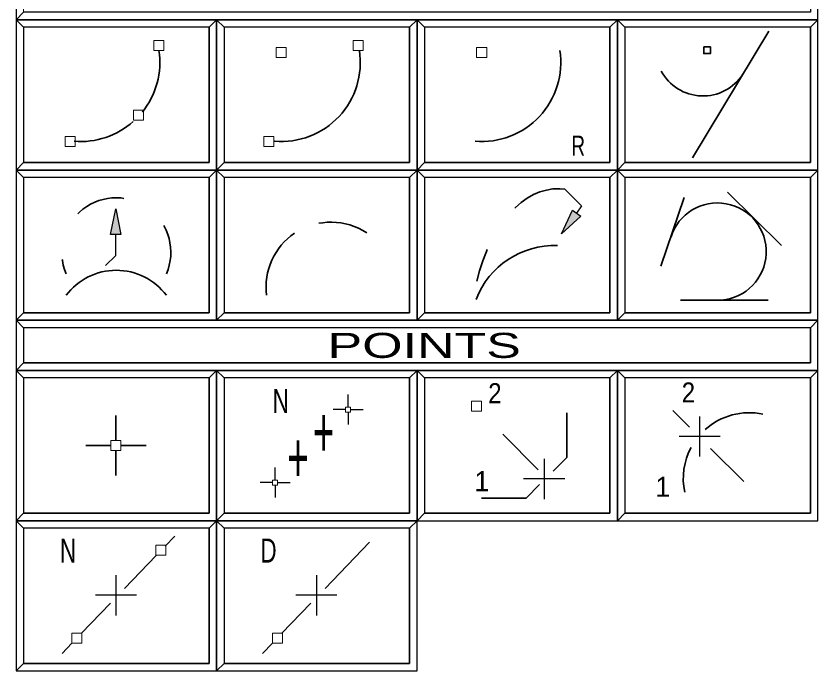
# Model space of a CAD drawing. Extents: x 95906.9 to 95918.9, y 90964.8 to 90972.9.
# Drawn here: x 95910.832 to 95912.432, y 90967.362 to 90968.669 of the extents above; entities that cross this region are included whole.
import ezdxf
from ezdxf.enums import TextEntityAlignment as Align

# ---------------------------------------------------------------- set-up
doc = ezdxf.new("R2010")
doc.units = 0
doc.header["$LTSCALE"] = 0.019
doc.linetypes.add('MEDIUM_DASHED', pattern=[4.5, 3, -1.5])
for name, color, linetype, lineweight in [('1', 7, 'Continuous', 25), ('11', 7, 'Continuous', 25), ('12', 7, 'Continuous', 25), ('17', 7, 'Continuous', 25), ('2', 7, 'Continuous', 13), ('3', 7, 'Continuous', 25), ('4', 7, 'Continuous', 35), ('6', 7, 'Continuous', 35), ('7', 7, 'Continuous', 35)]:
    doc.layers.add(name, color=color, linetype=linetype, lineweight=lineweight)

msp = doc.modelspace()

# ---------------------------------------------------------------- hatches: boundary and pattern name
at = {"layer": '6'}
for points in [[(95911.0204, 90968.2331), (95911.0306, 90968.2843), (95911.0408, 90968.2331)], [(95911.9585, 90968.2697), (95911.92, 90968.2344), (95911.9421, 90968.2817)]]:
    msp.add_hatch(color=256, dxfattribs=at).paths.add_polyline_path(points)

# ---------------------------------------------------------------- linework, layer by layer
at = {"layer": '1'}
for points in [[(95910.8318, 90968.6617), (95912.4318, 90968.6617), (95912.4318, 90968.7617), (95910.8318, 90968.7617)], [(95910.8318, 90968.3617), (95911.2318, 90968.3617), (95911.2318, 90968.6617), (95910.8318, 90968.6617)], [(95911.2318, 90968.3617), (95911.6318, 90968.3617), (95911.6318, 90968.6617), (95911.2318, 90968.6617)], [(95911.6318, 90968.3617), (95912.0318, 90968.3617), (95912.0318, 90968.6617), (95911.6318, 90968.6617)], [(95912.0318, 90968.3617), (95912.4318, 90968.3617), (95912.4318, 90968.6617), (95912.0318, 90968.6617)], [(95910.8318, 90968.0617), (95911.2318, 90968.0617), (95911.2318, 90968.3617), (95910.8318, 90968.3617)], [(95911.2318, 90968.0617), (95911.6318, 90968.0617), (95911.6318, 90968.3617), (95911.2318, 90968.3617)], [(95911.6318, 90968.0617), (95912.0318, 90968.0617), (95912.0318, 90968.3617), (95911.6318, 90968.3617)], [(95912.0318, 90968.0617), (95912.4318, 90968.0617), (95912.4318, 90968.3617), (95912.0318, 90968.3617)], [(95910.8318, 90967.9617), (95912.4318, 90967.9617), (95912.4318, 90968.0617), (95910.8318, 90968.0617)], [(95910.8318, 90967.6617), (95911.2318, 90967.6617), (95911.2318, 90967.9617), (95910.8318, 90967.9617)], [(95911.2318, 90967.6617), (95911.6318, 90967.6617), (95911.6318, 90967.9617), (95911.2318, 90967.9617)], [(95911.6318, 90967.6617), (95912.0318, 90967.6617), (95912.0318, 90967.9617), (95911.6318, 90967.9617)], [(95912.0318, 90967.6617), (95912.4318, 90967.6617), (95912.4318, 90967.9617), (95912.0318, 90967.9617)], [(95910.8318, 90967.3617), (95911.2318, 90967.3617), (95911.2318, 90967.6617), (95910.8318, 90967.6617)], [(95911.2318, 90967.3617), (95911.6318, 90967.3617), (95911.6318, 90967.6617), (95911.2318, 90967.6617)]]:
    msp.add_lwpolyline(points, close=True, dxfattribs=at)
at = {"layer": '11'}
for points in [[(95910.8468, 90968.3767), (95911.2168, 90968.3767), (95911.2168, 90968.6467), (95910.8468, 90968.6467)], [(95911.2468, 90968.3767), (95911.6168, 90968.3767), (95911.6168, 90968.6467), (95911.2468, 90968.6467)], [(95911.6468, 90968.3767), (95912.0168, 90968.3767), (95912.0168, 90968.6467), (95911.6468, 90968.6467)], [(95912.0468, 90968.3767), (95912.4168, 90968.3767), (95912.4168, 90968.6467), (95912.0468, 90968.6467)], [(95910.8468, 90968.0767), (95911.2168, 90968.0767), (95911.2168, 90968.3467), (95910.8468, 90968.3467)], [(95911.2468, 90968.0767), (95911.6168, 90968.0767), (95911.6168, 90968.3467), (95911.2468, 90968.3467)], [(95911.6468, 90968.0767), (95912.0168, 90968.0767), (95912.0168, 90968.3467), (95911.6468, 90968.3467)], [(95912.0468, 90968.0767), (95912.4168, 90968.0767), (95912.4168, 90968.3467), (95912.0468, 90968.3467)], [(95910.8468, 90967.6767), (95911.2168, 90967.6767), (95911.2168, 90967.9467), (95910.8468, 90967.9467)], [(95911.2468, 90967.6767), (95911.6168, 90967.6767), (95911.6168, 90967.9467), (95911.2468, 90967.9467)], [(95911.6468, 90967.6767), (95912.0168, 90967.6767), (95912.0168, 90967.9467), (95911.6468, 90967.9467)], [(95912.0468, 90967.6767), (95912.4168, 90967.6767), (95912.4168, 90967.9467), (95912.0468, 90967.9467)], [(95910.8468, 90967.3767), (95911.2168, 90967.3767), (95911.2168, 90967.6467), (95910.8468, 90967.6467)], [(95911.2468, 90967.3767), (95911.6168, 90967.3767), (95911.6168, 90967.6467), (95911.2468, 90967.6467)]]:
    msp.add_lwpolyline(points, close=True, dxfattribs=at)
at = {"layer": '12'}
for points in [[(95910.8468, 90968.3767), (95911.2168, 90968.3767), (95911.2168, 90968.6467), (95910.8468, 90968.6467)], [(95910.8468, 90967.6767), (95911.2168, 90967.6767), (95911.2168, 90967.9467), (95910.8468, 90967.9467)]]:
    msp.add_lwpolyline(points, close=True, dxfattribs=at)
at = {"layer": '17'}
msp.add_lwpolyline([(95910.8468, 90967.9767), (95912.4168, 90967.9767), (95912.4168, 90968.0467), (95910.8468, 90968.0467)], close=True, dxfattribs=at)
at = {"layer": '2'}
for points in [[(95910.8318, 90968.7617), (95910.8318, 90968.6617), (95910.8468, 90968.6767), (95910.8468, 90968.7467), (95912.4168, 90968.7467), (95912.4318, 90968.7617)], [(95910.8318, 90968.6617), (95910.8318, 90968.3617), (95910.8468, 90968.3767), (95910.8468, 90968.6467), (95911.2168, 90968.6467), (95911.2318, 90968.6617)], [(95911.2318, 90968.6617), (95911.2318, 90968.3617), (95911.2468, 90968.3767), (95911.2468, 90968.6467), (95911.6168, 90968.6467), (95911.6318, 90968.6617)], [(95911.6318, 90968.6617), (95911.6318, 90968.3617), (95911.6468, 90968.3767), (95911.6468, 90968.6467), (95912.0168, 90968.6467), (95912.0318, 90968.6617)], [(95912.0318, 90968.6617), (95912.0318, 90968.3617), (95912.0468, 90968.3767), (95912.0468, 90968.6467), (95912.4168, 90968.6467), (95912.4318, 90968.6617)], [(95910.8318, 90968.3617), (95910.8318, 90968.0617), (95910.8468, 90968.0767), (95910.8468, 90968.3467), (95911.2168, 90968.3467), (95911.2318, 90968.3617)], [(95911.2318, 90968.3617), (95911.2318, 90968.0617), (95911.2468, 90968.0767), (95911.2468, 90968.3467), (95911.6168, 90968.3467), (95911.6318, 90968.3617)], [(95911.6318, 90968.3617), (95911.6318, 90968.0617), (95911.6468, 90968.0767), (95911.6468, 90968.3467), (95912.0168, 90968.3467), (95912.0318, 90968.3617)], [(95912.0318, 90968.3617), (95912.0318, 90968.0617), (95912.0468, 90968.0767), (95912.0468, 90968.3467), (95912.4168, 90968.3467), (95912.4318, 90968.3617)], [(95910.8318, 90968.0617), (95910.8318, 90967.9617), (95910.8468, 90967.9767), (95910.8468, 90968.0467), (95912.4168, 90968.0467), (95912.4318, 90968.0617)], [(95910.8318, 90967.9617), (95910.8318, 90967.6617), (95910.8468, 90967.6767), (95910.8468, 90967.9467), (95911.2168, 90967.9467), (95911.2318, 90967.9617)], [(95911.2318, 90967.9617), (95911.2318, 90967.6617), (95911.2468, 90967.6767), (95911.2468, 90967.9467), (95911.6168, 90967.9467), (95911.6318, 90967.9617)], [(95911.6318, 90967.9617), (95911.6318, 90967.6617), (95911.6468, 90967.6767), (95911.6468, 90967.9467), (95912.0168, 90967.9467), (95912.0318, 90967.9617)], [(95912.0318, 90967.9617), (95912.0318, 90967.6617), (95912.0468, 90967.6767), (95912.0468, 90967.9467), (95912.4168, 90967.9467), (95912.4318, 90967.9617)], [(95910.8318, 90967.6617), (95910.8318, 90967.3617), (95910.8468, 90967.3767), (95910.8468, 90967.6467), (95911.2168, 90967.6467), (95911.2318, 90967.6617)], [(95911.2318, 90967.6617), (95911.2318, 90967.3617), (95911.2468, 90967.3767), (95911.2468, 90967.6467), (95911.6168, 90967.6467), (95911.6318, 90967.6617)]]:
    msp.add_lwpolyline(points, close=True, dxfattribs=at)
at = {"layer": '3'}
for points in [[(95910.8318, 90968.6617), (95912.4318, 90968.6617), (95912.4318, 90968.7617), (95912.4168, 90968.7467), (95912.4168, 90968.6767), (95910.8468, 90968.6767)], [(95910.8318, 90968.3617), (95911.2318, 90968.3617), (95911.2318, 90968.6617), (95911.2168, 90968.6467), (95911.2168, 90968.3767), (95910.8468, 90968.3767)], [(95911.2318, 90968.3617), (95911.6318, 90968.3617), (95911.6318, 90968.6617), (95911.6168, 90968.6467), (95911.6168, 90968.3767), (95911.2468, 90968.3767)], [(95911.6318, 90968.3617), (95912.0318, 90968.3617), (95912.0318, 90968.6617), (95912.0168, 90968.6467), (95912.0168, 90968.3767), (95911.6468, 90968.3767)], [(95912.0318, 90968.3617), (95912.4318, 90968.3617), (95912.4318, 90968.6617), (95912.4168, 90968.6467), (95912.4168, 90968.3767), (95912.0468, 90968.3767)], [(95910.8318, 90968.0617), (95911.2318, 90968.0617), (95911.2318, 90968.3617), (95911.2168, 90968.3467), (95911.2168, 90968.0767), (95910.8468, 90968.0767)], [(95911.2318, 90968.0617), (95911.6318, 90968.0617), (95911.6318, 90968.3617), (95911.6168, 90968.3467), (95911.6168, 90968.0767), (95911.2468, 90968.0767)], [(95911.6318, 90968.0617), (95912.0318, 90968.0617), (95912.0318, 90968.3617), (95912.0168, 90968.3467), (95912.0168, 90968.0767), (95911.6468, 90968.0767)], [(95912.0318, 90968.0617), (95912.4318, 90968.0617), (95912.4318, 90968.3617), (95912.4168, 90968.3467), (95912.4168, 90968.0767), (95912.0468, 90968.0767)], [(95910.8318, 90967.9617), (95912.4318, 90967.9617), (95912.4318, 90968.0617), (95912.4168, 90968.0467), (95912.4168, 90967.9767), (95910.8468, 90967.9767)], [(95910.8318, 90967.6617), (95911.2318, 90967.6617), (95911.2318, 90967.9617), (95911.2168, 90967.9467), (95911.2168, 90967.6767), (95910.8468, 90967.6767)], [(95911.2318, 90967.6617), (95911.6318, 90967.6617), (95911.6318, 90967.9617), (95911.6168, 90967.9467), (95911.6168, 90967.6767), (95911.2468, 90967.6767)], [(95911.6318, 90967.6617), (95912.0318, 90967.6617), (95912.0318, 90967.9617), (95912.0168, 90967.9467), (95912.0168, 90967.6767), (95911.6468, 90967.6767)], [(95912.0318, 90967.6617), (95912.4318, 90967.6617), (95912.4318, 90967.9617), (95912.4168, 90967.9467), (95912.4168, 90967.6767), (95912.0468, 90967.6767)], [(95910.8318, 90967.3617), (95911.2318, 90967.3617), (95911.2318, 90967.6617), (95911.2168, 90967.6467), (95911.2168, 90967.3767), (95910.8468, 90967.3767)], [(95911.2318, 90967.3617), (95911.6318, 90967.3617), (95911.6318, 90967.6617), (95911.6168, 90967.6467), (95911.6168, 90967.3767), (95911.2468, 90967.3767)]]:
    msp.add_lwpolyline(points, close=True, dxfattribs=at)
at = {"layer": '4'}
for p, q in [((95910.8468, 90968.6467), (95910.8318, 90968.6617)), ((95911.2468, 90968.6467), (95911.2318, 90968.6617)), ((95911.6468, 90968.6467), (95911.6318, 90968.6617)), ((95912.0468, 90968.6467), (95912.0318, 90968.6617)), ((95910.8468, 90968.3467), (95910.8318, 90968.3617)), ((95911.2468, 90968.3467), (95911.2318, 90968.3617)), ((95911.6468, 90968.3467), (95911.6318, 90968.3617)), ((95912.0468, 90968.3467), (95912.0318, 90968.3617)), ((95910.8468, 90968.0467), (95910.8318, 90968.0617)), ((95910.8468, 90967.9467), (95910.8318, 90967.9617)), ((95911.2468, 90967.9467), (95911.2318, 90967.9617)), ((95911.6468, 90967.9467), (95911.6318, 90967.9617)), ((95912.0468, 90967.9467), (95912.0318, 90967.9617)), ((95910.8468, 90967.6467), (95910.8318, 90967.6617)), ((95911.2468, 90967.6467), (95911.2318, 90967.6617))]:
    msp.add_line(p, q, dxfattribs=at)
at = {"layer": '6'}
for p, q in [((95912.1815, 90968.3864), (95912.334, 90968.6387)), ((95912.1182, 90968.1698), (95912.1646, 90968.3071)), ((95912.251, 90968.3178), (95912.3589, 90968.2108)), ((95912.3322, 90968.102), (95912.1574, 90968.102)), ((95912.142, 90967.8817), (95912.1756, 90967.8481)), ((95911.0312, 90967.8216), (95911.0312, 90967.8716)), ((95911.0212, 90967.8116), (95910.9712, 90967.8116)), ((95911.0412, 90967.8116), (95911.0912, 90967.8116)), ((95911.0312, 90967.8016), (95911.0312, 90967.7516)), ((95912.2836, 90967.74), (95912.2176, 90967.8061)), ((95911.1484, 90967.6305), (95911.1295, 90967.6108)), ((95911.4485, 90967.5266), (95911.537, 90967.6188)), ((95911.0485, 90967.5266), (95911.1117, 90967.5924)), ((95910.9617, 90967.4363), (95911.02, 90967.4969)), ((95911.3617, 90967.4363), (95911.42, 90967.4969)), ((95910.9238, 90967.3969), (95910.9434, 90967.4173)), ((95911.3238, 90967.3969), (95911.3434, 90967.4173))]:
    msp.add_line(p, q, dxfattribs=at)
at = {"layer": '6', "lineweight": 25}
for p, q in [((95911.4944, 90967.8886), (95911.4944, 90967.9136)), ((95911.4894, 90967.8836), (95911.4644, 90967.8836)), ((95911.4944, 90967.8786), (95911.4944, 90967.8536)), ((95911.4994, 90967.8836), (95911.5244, 90967.8836)), ((95912.1957, 90967.8699), (95912.1957, 90967.7896)), ((95912.1548, 90967.8305), (95912.2367, 90967.8305)), ((95911.8855, 90967.7853), (95911.8855, 90967.705)), ((95911.3486, 90967.7428), (95911.3486, 90967.7678)), ((95911.8446, 90967.7459), (95911.9265, 90967.7459)), ((95911.3436, 90967.7378), (95911.3186, 90967.7378)), ((95911.3486, 90967.7328), (95911.3486, 90967.7078)), ((95911.3536, 90967.7378), (95911.3786, 90967.7378)), ((95911.031, 90967.553), (95911.031, 90967.4727)), ((95911.431, 90967.553), (95911.431, 90967.4727)), ((95910.9901, 90967.5136), (95911.072, 90967.5136)), ((95911.3901, 90967.5136), (95911.472, 90967.5136))]:
    msp.add_line(p, q, dxfattribs=at)
at = {"layer": '6', "linetype": 'MEDIUM_DASHED'}
msp.add_line((95911.8738, 90967.7635), (95911.7588, 90967.8783), dxfattribs=at)
at = {"layer": '6', "lineweight": 13}
for points in [[(95911.1069, 90968.6005), (95911.1269, 90968.6005), (95911.1269, 90968.6205), (95911.1069, 90968.6205)], [(95911.5044, 90968.6001), (95911.5244, 90968.6001), (95911.5244, 90968.6201), (95911.5044, 90968.6201)], [(95911.3508, 90968.5865), (95911.3708, 90968.5865), (95911.3708, 90968.6065), (95911.3508, 90968.6065)], [(95911.7508, 90968.5865), (95911.7708, 90968.5865), (95911.7708, 90968.6065), (95911.7508, 90968.6065)], [(95911.0662, 90968.461), (95911.0862, 90968.461), (95911.0862, 90968.481), (95911.0662, 90968.481)], [(95910.9298, 90968.4086), (95910.9498, 90968.4086), (95910.9498, 90968.4286), (95910.9298, 90968.4286)], [(95911.326, 90968.4086), (95911.346, 90968.4086), (95911.346, 90968.4286), (95911.326, 90968.4286)], [(95911.4894, 90967.8786), (95911.4994, 90967.8786), (95911.4994, 90967.8886), (95911.4894, 90967.8886)], [(95911.7407, 90967.8806), (95911.7607, 90967.8806), (95911.7607, 90967.9006), (95911.7407, 90967.9006)], [(95911.0212, 90967.8016), (95911.0412, 90967.8016), (95911.0412, 90967.8216), (95911.0212, 90967.8216)], [(95911.3436, 90967.7328), (95911.3536, 90967.7328), (95911.3536, 90967.7428), (95911.3436, 90967.7428)], [(95911.111, 90967.5931), (95911.131, 90967.5931), (95911.131, 90967.6131), (95911.111, 90967.6131)], [(95910.9432, 90967.4175), (95910.9632, 90967.4175), (95910.9632, 90967.4375), (95910.9432, 90967.4375)], [(95911.3432, 90967.4175), (95911.3632, 90967.4175), (95911.3632, 90967.4375), (95911.3432, 90967.4375)]]:
    msp.add_lwpolyline(points, close=True, dxfattribs=at)
at = {"layer": '6'}
msp.add_lwpolyline([(95912.2038, 90968.6075), (95912.2172, 90968.6075), (95912.2172, 90968.5942), (95912.2038, 90968.5942)], close=True, dxfattribs=at)
at = {"layer": '6', "lineweight": 25}
for points in [[(95911.8989, 90968.3245), (95911.9258, 90968.3245), (95911.9603, 90968.29), (95911.95, 90968.2758)], [(95911.0105, 90968.1711), (95911.0306, 90968.1912), (95911.0306, 90968.2331)]]:
    msp.add_lwpolyline(points, dxfattribs=at)
for points in [[(95911.0204, 90968.2331), (95911.0306, 90968.2843), (95911.0408, 90968.2331)], [(95911.9585, 90968.2697), (95911.92, 90968.2344), (95911.9421, 90968.2817)]]:
    msp.add_lwpolyline(points, close=True, dxfattribs=at)
at = {"layer": '6'}
for points in [[(95911.9035, 90967.7609), (95911.9306, 90967.7881), (95911.9305, 90967.8772)], [(95911.8764, 90967.7338), (95911.8493, 90967.7067), (95911.7602, 90967.7067)]]:
    msp.add_lwpolyline(points, dxfattribs=at)
for centre, radius, start, end in [((95910.9608, 90968.5765), 0.1579, 321.1842, 8.7525), ((95911.3608, 90968.5765), 0.1579, 265.2424, 8.7525), ((95911.7608, 90968.5765), 0.1579, 265.2424, 8.7525), ((95912.2025, 90968.6043), 0.0947, 208.2947, 327.2812), ((95910.9608, 90968.5765), 0.1579, 265.2424, 311.6125), ((95912.2313, 90968.1989), 0.0972, 274.8279, 162.46), ((95911.4601, 90968.1283), 0.1294, 124.0311, 187.3672), ((95911.906, 90968.0437), 0.1674, 87.8498, 159.0411), ((95911.0318, 90968.0367), 0.125, 36.8699, 143.1301), ((95912.2948, 90967.7457), 0.1317, 78.0876, 132.0346), ((95912.2948, 90967.7457), 0.1317, 151.6888, 191.9492)]:
    msp.add_arc(centre, radius, start, end, dxfattribs=at)
at = {"layer": '6', "linetype": 'MEDIUM_DASHED'}
for centre, radius, start, end in [((95911.0318, 90968.1975), 0.1088, 336.7954, 203.2046), ((95911.4602, 90968.1282), 0.1295, 56.5459, 121.945)]:
    msp.add_arc(centre, radius, start, end, dxfattribs=at)
msp.add_ellipse((95911.906, 90968.0437), major_axis=(0.0105, 0.2807), ratio=0.595849, start_param=6.283185, end_param=7.525708, dxfattribs=at)

# ---------------------------------------------------------------- texts
at = {"layer": '6'}
for s, height, width, p in [('R', 0.04, 0.7, (95911.9535, 90968.3904)), ('2', 0.04, 0.9, (95911.7872, 90967.8963)), ('2', 0.04, 0.9, (95912.1733, 90967.8977)), ('N', 0.048, 0.7, (95911.3599, 90967.8769)), ('+', 0.1, 0.55, (95911.4453, 90967.789)), ('+', 0.1, 0.55, (95911.3942, 90967.738)), ('N', 0.048, 0.7, (95910.9355, 90967.5781)), ('D', 0.048, 0.7, (95911.3355, 90967.5781))]:
    msp.add_text(s, height=height, dxfattribs=dict(at, width=width)).set_placement(p, align=Align.CENTER)
for p in [(95911.7612, 90967.7206), (95912.1222, 90967.7095)]:
    msp.add_text('1', height=0.04, dxfattribs=at).set_placement(p, align=Align.CENTER)
at = {"layer": '7', "width": 1.55}
msp.add_text('         POINTS        ', height=0.04999, dxfattribs=at).set_placement((95911.6318, 90967.9867), align=Align.CENTER)

doc.saveas('drawing.dxf')
